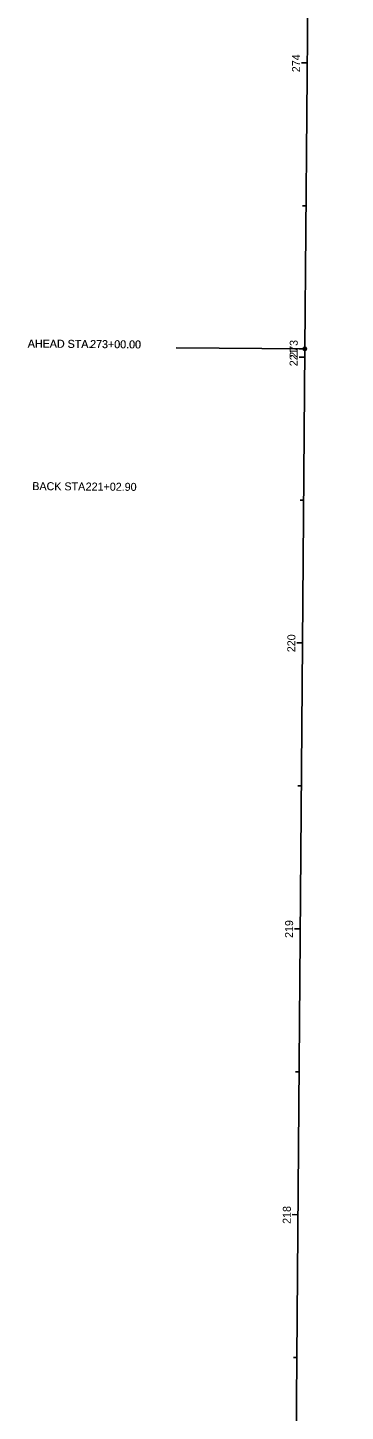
# Model space of a CAD drawing. Extents: x 1504466 to 1504712, y 322450 to 329957.
# Drawn here: x 1504465.5 to 1504576.7, y 323383.8 to 323867.8 of the extents above; entities that cross this region are included whole.
import ezdxf

# ---------------------------------------------------------------- set-up
doc = ezdxf.new("R2010")
doc.units = 0
for name, color, linetype in [('GE_X_Alignment', 7, 'Continuous'), ('GE_X_Alignment_100_Cardinal_Points', 7, 'Continuous'), ('GE_X_Alignment_100_Stations', 7, 'Continuous'), ('GE_X_Alignment_500_Cardinal_Points', 7, 'Continuous'), ('GE_X_Alignment_500_Stations', 7, 'Continuous')]:
    doc.layers.add(name, color=color, linetype=linetype)

msp = doc.modelspace()

# ---------------------------------------------------------------- linework, layer by layer
at = {"layer": 'GE_X_Alignment'}
for p, q in [((1504562.54, 323755.45), (1504576.71, 325454.21)), ((1504552.13, 322452.59), (1504562.54, 323755.45))]:
    msp.add_line(p, q, dxfattribs=at)
at = {"layer": 'GE_X_Alignment_100_Cardinal_Points'}
for q in [(1504517.54, 323755.83), (1504517.54, 323755.81)]:
    msp.add_line((1504562.54, 323755.45), q, dxfattribs=at)
msp.add_circle((1504562.54, 323755.45), 0.6, dxfattribs=at)
msp.add_circle((1504562.54, 323755.45), 0.6, dxfattribs=at)
at = {"layer": 'GE_X_Alignment_100_Stations'}
for p, q in [((1504563.38, 323855.45), (1504561.38, 323855.47)), ((1504562.96, 323805.45), (1504561.76, 323805.46)), ((1504562.52, 323752.55), (1504560.52, 323752.57)), ((1504562.54, 323755.45), (1504560.54, 323755.47)), ((1504562.12, 323702.55), (1504560.92, 323702.56)), ((1504561.72, 323652.55), (1504559.72, 323652.57)), ((1504561.32, 323602.55), (1504560.12, 323602.56)), ((1504560.92, 323552.56), (1504558.92, 323552.57)), ((1504560.52, 323502.56), (1504559.32, 323502.57)), ((1504560.12, 323452.56), (1504558.12, 323452.58)), ((1504559.72, 323402.56), (1504558.52, 323402.57))]:
    msp.add_line(p, q, dxfattribs=at)
at = {"layer": 'GE_X_Alignment_500_Cardinal_Points'}
for q in [(1504517.54, 323755.83), (1504517.54, 323755.81)]:
    msp.add_line((1504562.54, 323755.45), q, dxfattribs=at)
msp.add_circle((1504562.54, 323755.45), 0.6, dxfattribs=at)
msp.add_circle((1504562.54, 323755.45), 0.6, dxfattribs=at)
at = {"layer": 'GE_X_Alignment_500_Stations'}
for p, q in [((1504563.38, 323855.45), (1504562.18, 323855.46)), ((1504562.52, 323752.55), (1504561.32, 323752.56)), ((1504562.54, 323755.45), (1504561.34, 323755.46)), ((1504561.72, 323652.55), (1504559.72, 323652.57)), ((1504560.92, 323552.56), (1504559.72, 323552.57)), ((1504560.12, 323452.56), (1504558.92, 323452.57))]:
    msp.add_line(p, q, dxfattribs=at)

# ---------------------------------------------------------------- texts
at = {"layer": 'GE_X_Alignment_100_Cardinal_Points'}
for s, rotation, p in [('AHEAD STA. ', 359.5221, (1504465.61, 323755.91)), ('273+00.00', 359.5221, (1504487.43, 323755.73)), ('BACK STA. ', 359.5421, (1504467.17, 323706.03)), ('221+02.90', 359.5421, (1504485.86, 323705.88))]:
    msp.add_text(s, height=2.8, rotation=rotation, dxfattribs=at).set_placement(p)
at = {"layer": 'GE_X_Alignment_100_Stations'}
for s, rotation, p in [('274', 89.5221, (1504560.85, 323852.19)), ('273', 89.5221, (1504560.01, 323752.28)), ('221', 89.5421, (1504559.99, 323749.35)), ('220', 89.5421, (1504559.19, 323649.31)), ('219', 89.5421, (1504558.39, 323549.35)), ('218', 89.5421, (1504557.6, 323449.33))]:
    msp.add_text(s, height=2.8, rotation=rotation, dxfattribs=at).set_placement(p)
at = {"layer": 'GE_X_Alignment_500_Cardinal_Points'}
for s, rotation, p in [('AHEAD STA. ', 359.5221, (1504465.53, 323755.9)), ('273+00.00', 359.5221, (1504487.35, 323755.72)), ('BACK STA. ', 359.5421, (1504467.14, 323706.03)), ('221+02.90', 359.5421, (1504485.83, 323705.88))]:
    msp.add_text(s, height=2.8, rotation=rotation, dxfattribs=at).set_placement(p)
at = {"layer": 'GE_X_Alignment_500_Stations'}
msp.add_text('220', height=2.8, rotation=89.5421, dxfattribs=at).set_placement((1504559.19, 323649.31))

doc.saveas('drawing.dxf')
